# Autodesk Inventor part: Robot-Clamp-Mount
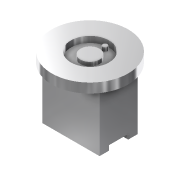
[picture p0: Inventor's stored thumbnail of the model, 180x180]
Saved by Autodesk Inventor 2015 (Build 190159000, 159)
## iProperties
Shininess: 21.0
Length Units: 11269
Angle Units: 11279
Time Units: 11290
Mass Units: 11283
Length Display Precision: 3
Angle Display Precision: 2
Created: 2001-08
Part Number: Robot-Clamp-Mount
Document SubType Name: ﾓﾃﾞﾘﾝｸﾞ
Designer: Administrator
Density: 1 g/cm^3
Material: Generic
Appearance: Chrome - Polished
Density: 0.0
Volumn: 0.0
Area: 0.0
PropertySet Name: Model Information
Control State: 0
Master: False
Checked Out: False
Author: Administrator
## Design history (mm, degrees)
workplane "Work Plane1"
body "Solid1"
sketch "ｽｹｯﾁ1"
  geometry: C1 r 40 at (-1.046, 0.586)
  constraints: 1 centre point
  dimensions: "d0" = 80 diameter of C1
extrude "Extrusion1" new body sketch "ｽｹｯﾁ1" distance "d1" = 10; taper "d2" = 0 deg
sketch "ｽｹｯﾁ2"
  geometry: L1 (0, 15.75)-(0, 0); C1 r 40 at (0, 0) reference; C2 r 20 at (0, 0)
  constraints: 2 coincident, 2 end point, 1 centre point, 1 vertical
  dimensions: "d17" = 40 diameter of C2
extrude "Extrusion2" cut sketch "ｽｹｯﾁ2" distance "d7" = 6.5; taper "d8" = 0 deg
sketch "ｽｹｯﾁ3"
  geometry: L1 (-30, 20)-(30, 20); L2 (30, 20)-(30, -20); L3 (30, -20)-(-30, -20); L4 (-30, -20)-(-30, 20); L5 (-30, 0)-(30, 0); L6 (0, 20)-(0, -20); C1 r 40 at (0, 0) reference; 2 further points
  constraints: 12 end point, 5 midpoint, 2 coincident, 2 parallel, 1 horizontal, 1 perpendicular, 1 other
  dimensions: "d9" = 40 distance of L3.end L1.start; "d10" = 60 distance of L1.start L1.end
extrude "Extrusion3" join sketch "ｽｹｯﾁ3" distance "d11" = 60; taper "d12" = 0 deg
sketch "ｽｹｯﾁ4"
  geometry: L1 (-30, 20)-(30, 20) reference; L2 (-30, -20)-(-30, 20) reference; L3 (30, 20)-(30, -20) reference; L4 (-30, 10)-(30, 10); L5 (30, 10)-(30, -10); L6 (30, -10)-(-30, -10); L7 (-30, -10)-(-30, 10)
  constraints: 8 end point, 2 parallel, 2 point on line, 1 horizontal, 1 perpendicular
  dimensions: "d13" = 20 distance between parallel lines of L6 L4; "d14" = 10 distance between parallel lines of L4 L1
extrude "Extrusion4" cut sketch "ｽｹｯﾁ4" distance "d15" = 5; taper "d16" = 0 deg
sketch "ｽｹｯﾁ5"
  geometry: L1 (0, 0)-(0, 15.75); C1 r 20 at (0, 0) reference; C2 r 10 at (0, 0); C3 r 2.5 at (0, 15.75)
  constraints: 2 centre point, 2 coincident, 2 end point, 1 vertical
  dimensions: "d18" = 20 diameter of C2; "d19" = 15.75 distance of L1.start L1.end; "d20" = 5 diameter of C3
extrude "Extrusion5" join sketch "ｽｹｯﾁ5" distance "d21" = 4; taper "d22" = 0 deg
